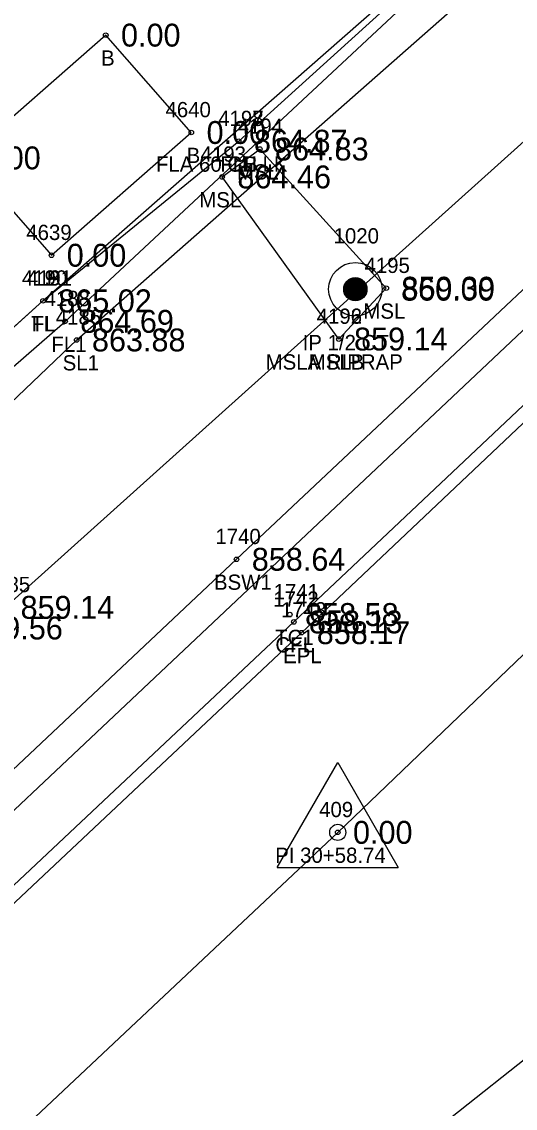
# Model space of a CAD drawing. Extents: x 1622501 to 1626664, y 1117816 to 1121579.
# Drawn here: x 1625103.9 to 1625136.3, y 1120306.8 to 1120378.1 of the extents above; entities that cross this region are included whole.
import ezdxf

# ---------------------------------------------------------------- set-up
doc = ezdxf.new("R2010")
doc.units = 0
for name, color, linetype in [('RD_EX_Bldg', 7, 'Continuous'), ('RD_EX_Bldg_txCode', 7, 'Continuous'), ('RD_EX_Conc', 7, 'Continuous'), ('RD_EX_Conc_txCode', 7, 'Continuous'), ('RD_EX_DR_Pipe', 7, 'Continuous'), ('RD_EX_DV_Prop_txCode', 7, 'Continuous'), ('RD_EX_DV_PropPin', 7, 'Continuous'), ('RD_EX_Fence_Other', 7, 'Continuous'), ('RD_EX_Fence_Other_txCode', 7, 'Continuous'), ('RD_EX_Misc', 7, 'Continuous'), ('RD_EX_Misc_txCode', 7, 'Continuous'), ('RD_EX_Road', 7, 'Continuous'), ('RD_EX_Road_txCode', 7, 'Continuous'), ('RD_EX_TX_Bldg_ELEV', 7, 'Continuous'), ('RD_EX_TX_Conc_ELEV', 7, 'Continuous'), ('RD_EX_TX_DV_Prop_ELEV', 7, 'Continuous'), ('RD_EX_TX_Fence_Other_ELEV', 7, 'Continuous'), ('RD_EX_TX_Misc_ELEV', 7, 'Continuous'), ('RD_EX_TX_Road_ELEV', 7, 'Continuous'), ('RD_EX_TX_VEG_ELEV', 7, 'Continuous'), ('RD_EX_VEG', 7, 'Continuous'), ('RD_EX_VEG_txCode', 7, 'Continuous'), ('RD_HC_Cl', 7, 'Continuous'), ('RD_HC_Data', 7, 'Continuous'), ('RD_HC_Survey_ELEV', 7, 'Continuous'), ('RD_HC_txCode', 7, 'Continuous'), ('RD_SMD_Locator', 7, 'Continuous')]:
    doc.layers.add(name, color=color, linetype=linetype)

msp = doc.modelspace()

# ---------------------------------------------------------------- linework, layer by layer
at = {"layer": 'RD_EX_Bldg'}
msp.add_lwpolyline([(1625100.292, 1120369.177), (1625105.901, 1120362.791), (1625115.068, 1120370.843), (1625109.458, 1120377.229), (1625100.292, 1120369.177)], dxfattribs=at)
at = {"layer": 'RD_EX_Conc'}
for points in [[(1624897.378, 1120127.586), (1624903.697, 1120133.247), (1624939.766, 1120167.411), (1624977.137, 1120202.764), (1625013.589, 1120237.139), (1625049.488, 1120270.838), (1625084.275, 1120303.479), (1625121.787, 1120338.741), (1625157.607, 1120372.541), (1625193.027, 1120405.896), (1625230.27, 1120441.109), (1625263.987, 1120473.049), (1625301.798, 1120509.249), (1625336.15, 1120542.221), (1625372.25, 1120576.993), (1625405.365, 1120609.311), (1625409.32, 1120614.519), (1625412.456, 1120620.32), (1625414.419, 1120627.016), (1625414.966, 1120636.138), (1625412.914, 1120644.37), (1625411.037, 1120648.086), (1625399.274, 1120667.189)], [(1624899.89, 1120137.526), (1624936.243, 1120171.696), (1624973.261, 1120206.726), (1625009.729, 1120241.184), (1625045.817, 1120275.099), (1625080.725, 1120307.719), (1625118.033, 1120342.848), (1625154.459, 1120377.147), (1625189.451, 1120410.103), (1625226.397, 1120445.046), (1625260.082, 1120477.093), (1625298.209, 1120513.612), (1625332.486, 1120546.411), (1625368.395, 1120580.995), (1625401.296, 1120613.087), (1625404.616, 1120617.809), (1625407.287, 1120622.414), (1625408.963, 1120627.094), (1625409.263, 1120635.885), (1625414.414, 1120636.083)]]:
    msp.add_lwpolyline(points, dxfattribs=at)
at = {"layer": 'RD_EX_DR_Pipe'}
msp.add_lwpolyline([(1625495.159, 1120700.169), (1625478.481, 1120693.944), (1625478.481, 1120693.944), (1625401.274, 1120618.609), (1625386.855, 1120595.889), (1625386.855, 1120595.889), (1625239.336, 1120454.576), (1625067.489, 1120292.506), (1624913.323, 1120147.082), (1624906.318, 1120142.577), (1624803.571, 1120043.734), (1624612.212, 1119870.34), (1624528.295, 1119793.118)], dxfattribs=at)
at = {"layer": 'RD_EX_DV_PropPin'}
for p, q in [((1625125.158, 1120360.194), (1625125.158, 1120360.933)), ((1625125.193, 1120360.137), (1625125.193, 1120360.99)), ((1625125.228, 1120360.09), (1625125.228, 1120361.038)), ((1625125.263, 1120360.049), (1625125.263, 1120361.079)), ((1625125.298, 1120360.013), (1625125.298, 1120361.114)), ((1625125.333, 1120359.982), (1625125.333, 1120361.146)), ((1625125.368, 1120359.954), (1625125.368, 1120361.174)), ((1625125.403, 1120359.929), (1625125.403, 1120361.198)), ((1625125.438, 1120359.907), (1625125.438, 1120361.22)), ((1625125.473, 1120359.888), (1625125.473, 1120361.239)), ((1625125.508, 1120359.871), (1625125.508, 1120361.256)), ((1625125.543, 1120359.856), (1625125.543, 1120361.271)), ((1625125.578, 1120359.843), (1625125.578, 1120361.284)), ((1625125.613, 1120359.832), (1625125.613, 1120361.295)), ((1625125.648, 1120359.823), (1625125.648, 1120361.304)), ((1625125.683, 1120359.816), (1625125.683, 1120361.312)), ((1625125.718, 1120359.81), (1625125.718, 1120361.317)), ((1625125.753, 1120359.806), (1625125.753, 1120361.321)), ((1625125.788, 1120359.803), (1625125.788, 1120361.324)), ((1625125.823, 1120359.803), (1625125.823, 1120361.325)), ((1625125.858, 1120359.803), (1625125.858, 1120361.324)), ((1625125.893, 1120359.806), (1625125.893, 1120361.321)), ((1625125.928, 1120359.81), (1625125.928, 1120361.317)), ((1625125.963, 1120359.816), (1625125.963, 1120361.312)), ((1625125.998, 1120359.823), (1625125.998, 1120361.304)), ((1625126.033, 1120359.832), (1625126.033, 1120361.295)), ((1625126.068, 1120359.843), (1625126.068, 1120361.284)), ((1625126.103, 1120359.856), (1625126.103, 1120361.271)), ((1625126.138, 1120359.871), (1625126.138, 1120361.256)), ((1625126.173, 1120359.888), (1625126.173, 1120361.239)), ((1625126.208, 1120359.907), (1625126.208, 1120361.22)), ((1625126.243, 1120359.929), (1625126.243, 1120361.198)), ((1625126.278, 1120359.954), (1625126.278, 1120361.174)), ((1625126.313, 1120359.982), (1625126.313, 1120361.146)), ((1625126.348, 1120360.013), (1625126.348, 1120361.114)), ((1625126.384, 1120360.049), (1625126.384, 1120361.079)), ((1625126.419, 1120360.09), (1625126.419, 1120361.038)), ((1625126.454, 1120360.137), (1625126.454, 1120360.99)), ((1625126.489, 1120360.194), (1625126.489, 1120360.933)), ((1625125.088, 1120360.368), (1625125.088, 1120360.76)), ((1625125.123, 1120360.266), (1625125.123, 1120360.862)), ((1625126.524, 1120360.266), (1625126.524, 1120360.862)), ((1625126.559, 1120360.368), (1625126.559, 1120360.76))]:
    msp.add_line(p, q, dxfattribs=at)
for radius in [1.75, 0.761]:
    msp.add_circle((1625125.823, 1120360.564), radius, dxfattribs=at)
at = {"layer": 'RD_EX_Fence_Other'}
for points in [[(1624882.108, 1120146.413), (1624922.827, 1120188.172), (1624952.576, 1120216.9), (1624993.862, 1120256.562), (1625030.931, 1120289.642), (1625069.578, 1120325.996), (1625106.791, 1120358.455), (1625145.388, 1120394.48), (1625163.872, 1120411.002), (1625180.046, 1120426.703), (1625211.372, 1120456.62), (1625250.442, 1120494.547), (1625284.568, 1120527.631), (1625318.686, 1120557.977), (1625317.764, 1120559.821), (1625354.436, 1120595.487), (1625389.434, 1120629.691)], [(1624968.412, 1120251.923), (1624973.485, 1120246.613), (1625017.999, 1120286.663), (1625019.131, 1120285.989), (1625066.231, 1120328.946), (1625069.089, 1120326.051), (1625069.144, 1120326.972), (1625105.343, 1120359.801), (1625118.176, 1120370.27), (1625118.176, 1120370.27), (1625145.005, 1120394.595), (1625165.443, 1120413.584)]]:
    msp.add_lwpolyline(points, dxfattribs=at)
at = {"layer": 'RD_EX_Misc'}
msp.add_lwpolyline([(1625124.737, 1120357.294), (1625117.092, 1120367.929), (1625119.558, 1120369.759), (1625127.852, 1120360.629), (1625124.737, 1120357.294)], dxfattribs=at)
at = {"layer": 'RD_EX_Road'}
for points in [[(1624781.367, 1120199.017), (1624784.165, 1120188.994), (1624788.317, 1120183.838), (1624819.769, 1120157.812), (1624850.784, 1120132.057), (1624863.119, 1120123.17), (1624872.562, 1120120.776), (1624881.482, 1120120.158), (1624884.455, 1120120.692), (1624898.026, 1120126.784), (1624903.404, 1120131.449), (1624903.183, 1120131.678), (1624904.185, 1120132.725), (1624940.396, 1120166.874), (1624977.651, 1120202.124), (1625014.07, 1120236.514), (1625050.075, 1120270.322), (1625084.777, 1120302.734), (1625122.295, 1120338.035), (1625158.189, 1120371.975), (1625193.609, 1120405.268), (1625230.886, 1120440.454)], [(1624481.686, 1119706.573), (1624518.072, 1119740.622), (1624554.525, 1119774.632), (1624590.986, 1119808.778), (1624627.133, 1119843.173), (1624664.125, 1119876.781), (1624700.281, 1119911.275), (1624736.97, 1119945.679), (1624773.625, 1119979.796), (1624810.113, 1120014.451), (1624846.423, 1120048.907), (1624882.768, 1120083.191), (1624919.142, 1120117.136), (1624955.414, 1120151.754), (1624991.664, 1120186.106), (1625027.75, 1120220.093), (1625065.425, 1120252.962), (1625104.19, 1120284.121), (1625143.204, 1120315.036), (1625181.69, 1120345.902), (1625220.314, 1120377.13)]]:
    msp.add_lwpolyline(points, dxfattribs=at)
at = {"layer": 'RD_EX_VEG'}
for points in [[(1624992.75, 1120261.436), (1624994.015, 1120256.481), (1625045.588, 1120300.866), (1625059.123, 1120303.266), (1625063.507, 1120321.975), (1625105.343, 1120359.801), (1625167.773, 1120414.629), (1625284.568, 1120527.631), (1625296.639, 1120540.301), (1625291.874, 1120545.154)], [(1625096.903, 1120347.066), (1625102.874, 1120339.698), (1625152.178, 1120384.03), (1625170.927, 1120401.075), (1625165.695, 1120409.022)], [(1625096.903, 1120347.066), (1625107.552, 1120357.235), (1625146.826, 1120391.831), (1625165.695, 1120409.022)]]:
    msp.add_lwpolyline(points, dxfattribs=at)
at = {"layer": 'RD_HC_Cl'}
for p, q in [((1625124.669, 1120324.937), (1625539.123, 1120722.158)), ((1624870.491, 1120085.684), (1625124.669, 1120324.937))]:
    msp.add_line(p, q, dxfattribs=at)
at = {"layer": 'RD_HC_Data'}
for p, q in [((1625120.698, 1120322.644), (1625124.67, 1120329.524)), ((1625124.67, 1120329.524), (1625128.639, 1120322.644)), ((1625120.698, 1120322.644), (1625128.639, 1120322.644))]:
    msp.add_line(p, q, dxfattribs=at)
msp.add_circle((1625124.669, 1120324.937), 0.529, dxfattribs=at)
at = {"layer": 'RD_SMD_Locator'}
for centre in [(1625109.458, 1120377.229), (1625115.068, 1120370.843), (1625118.176, 1120370.27), (1625118.176, 1120370.27), (1625119.558, 1120369.759), (1625117.092, 1120367.929), (1625105.901, 1120362.791), (1625125.823, 1120360.564), (1625127.852, 1120360.629), (1625105.343, 1120359.801), (1625105.343, 1120359.801), (1625106.791, 1120358.455), (1625107.552, 1120357.235), (1625124.737, 1120357.294), (1625124.737, 1120357.294), (1625118.033, 1120342.848), (1625121.526, 1120339.224), (1625121.787, 1120338.741), (1625122.295, 1120338.035), (1625124.669, 1120324.937)]:
    msp.add_circle(centre, 0.15, dxfattribs=at)

# ---------------------------------------------------------------- texts
at = {"layer": 'RD_EX_Bldg_txCode'}
for s, p in [('B', (1625109.151, 1120375.229)), ('4640', (1625113.375, 1120371.843)), ('B', (1625114.761, 1120368.843)), ('4639', (1625104.248, 1120363.791)), ('B', (1625105.594, 1120360.791))]:
    msp.add_text(s, height=1, dxfattribs=at).set_placement(p)
at = {"layer": 'RD_EX_Conc_txCode'}
for s, p in [('1740', (1625116.647, 1120343.848)), ('BSW1', (1625116.553, 1120340.848)), ('1741', (1625120.463, 1120340.224)), ('1742', (1625120.441, 1120339.741)), ('TC1', (1625120.566, 1120337.224)), ('CFL', (1625120.582, 1120336.741))]:
    msp.add_text(s, height=1, dxfattribs=at).set_placement(p)
at = {"layer": 'RD_EX_DV_Prop_txCode'}
for s, p in [('1020', (1625124.398, 1120363.564)), ('IP 1/2 CT', (1625122.367, 1120356.564))]:
    msp.add_text(s, height=1, dxfattribs=at).set_placement(p)
at = {"layer": 'RD_EX_Fence_Other_txCode'}
for s, p in [('4197', (1625116.83, 1120371.27)), ('4198', (1625116.83, 1120371.27)), ('FLA 60 CH LK', (1625112.751, 1120368.27)), ('FLB', (1625116.972, 1120368.27)), ('4190', (1625103.957, 1120360.801)), ('4188', (1625105.444, 1120359.455)), ('FL', (1625104.61, 1120357.801)), ('FL1', (1625105.893, 1120356.455))]:
    msp.add_text(s, height=1, dxfattribs=at).set_placement(p)
at = {"layer": 'RD_EX_Misc_txCode'}
for s, p in [('4194', (1625118.106, 1120370.759)), ('4193', (1625115.676, 1120368.929)), ('MSL', (1625118.055, 1120367.759)), ('MSL', (1625115.59, 1120365.929)), ('4195', (1625126.423, 1120361.629)), ('MSL', (1625126.35, 1120358.629)), ('4196', (1625123.288, 1120358.294)), ('4192', (1625123.29, 1120358.294)), ('MSLA RIPRAP', (1625119.942, 1120355.294)), ('MSLB', (1625122.767, 1120355.294))]:
    msp.add_text(s, height=1, dxfattribs=at).set_placement(p)
at = {"layer": 'RD_EX_Road_txCode'}
for s, p in [('1743', (1625120.948, 1120339.035)), ('EPL', (1625121.09, 1120336.035))]:
    msp.add_text(s, height=1, dxfattribs=at).set_placement(p)
at = {"layer": 'RD_EX_TX_Bldg_ELEV'}
for p in [(1625110.458, 1120376.479), (1625116.068, 1120370.093), (1625101.292, 1120368.427), (1625101.292, 1120368.427), (1625106.901, 1120362.041)]:
    msp.add_text('0.00', height=1.5, dxfattribs=at).set_placement(p)
at = {"layer": 'RD_EX_TX_Conc_ELEV'}
for s, p in [('858.64', (1625119.033, 1120342.098)), ('858.58', (1625122.526, 1120338.474)), ('858.13', (1625122.787, 1120337.991))]:
    msp.add_text(s, height=1.5, dxfattribs=at).set_placement(p)
at = {"layer": 'RD_EX_TX_DV_Prop_ELEV'}
msp.add_text('860.00', height=1.5, dxfattribs=at).set_placement((1625128.823, 1120359.814))
at = {"layer": 'RD_EX_TX_Fence_Other_ELEV'}
for s, p in [('864.87', (1625119.176, 1120369.52)), ('864.87', (1625119.176, 1120369.52)), ('865.02', (1625106.343, 1120359.051)), ('864.69', (1625107.791, 1120357.705))]:
    msp.add_text(s, height=1.5, dxfattribs=at).set_placement(p)
at = {"layer": 'RD_EX_TX_Misc_ELEV'}
for s, p in [('864.83', (1625120.558, 1120369.009)), ('864.46', (1625118.092, 1120367.179)), ('859.39', (1625128.852, 1120359.879)), ('859.14', (1625125.737, 1120356.544)), ('859.14', (1625125.737, 1120356.544))]:
    msp.add_text(s, height=1.5, dxfattribs=at).set_placement(p)
at = {"layer": 'RD_EX_TX_Road_ELEV'}
msp.add_text('858.17', height=1.5, dxfattribs=at).set_placement((1625123.295, 1120337.285))
at = {"layer": 'RD_EX_TX_VEG_ELEV'}
for s, p in [('865.02', (1625106.343, 1120359.051)), ('863.88', (1625108.552, 1120356.485)), ('859.14', (1625103.874, 1120338.948)), ('859.56', (1625100.509, 1120337.591))]:
    msp.add_text(s, height=1.5, dxfattribs=at).set_placement(p)
at = {"layer": 'RD_EX_VEG_txCode'}
for s, p in [('4191', (1625104.28, 1120360.801)), ('TL', (1625104.571, 1120357.801)), ('4186', (1625106.182, 1120358.235)), ('SL1', (1625106.631, 1120355.235)), ('4185', (1625101.528, 1120340.698))]:
    msp.add_text(s, height=1, dxfattribs=at).set_placement(p)
at = {"layer": 'RD_HC_Survey_ELEV'}
msp.add_text('0.00', height=1.5, dxfattribs=at).set_placement((1625125.669, 1120324.187))
at = {"layer": 'RD_HC_txCode'}
for s, p in [('409', (1625123.449, 1120325.937)), ('PI 30+58.74', (1625120.567, 1120322.937))]:
    msp.add_text(s, height=1, dxfattribs=at).set_placement(p)

doc.saveas('drawing.dxf')
